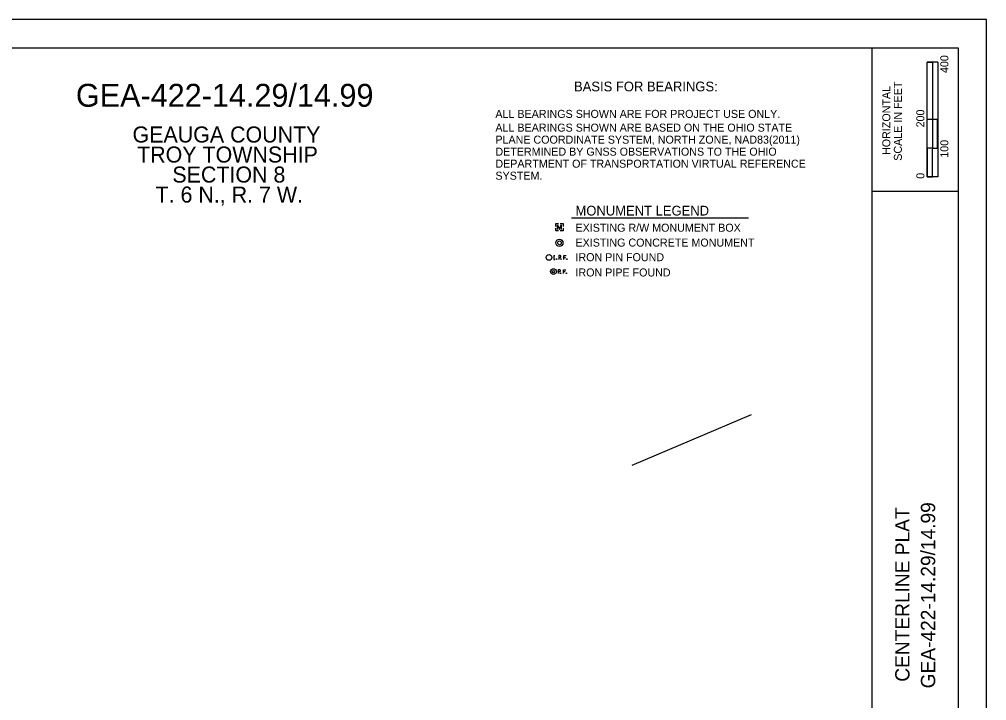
# Model space of a CAD drawing. Extents: x -4.4 to 34, y -1.2 to 22.
# Drawn here: x 17.08 to 34, y 10.09 to 22 of the extents above; entities that cross this region are included whole.
import ezdxf

# ---------------------------------------------------------------- set-up
doc = ezdxf.new("R2010")
doc.units = 0
for name, color, linetype in [('DV_X_Section_VMS_Line', 7, 'Continuous'), ('SH_Border', 7, 'Continuous'), ('SH_Cut_Line', 7, 'Continuous'), ('SH_Named_Boundary', 7, 'Continuous'), ('SH_Text', 7, 'Continuous')]:
    doc.layers.add(name, color=color, linetype=linetype)

msp = doc.modelspace()

# ---------------------------------------------------------------- linework, layer by layer
at = {"layer": 'DV_X_Section_VMS_Line'}
msp.add_line((27.797, 14.21), (29.889, 15.092), dxfattribs=at)
at = {"layer": 'SH_Border'}
for p, q in [((32, 0.5), (32, 21.5)), ((32, 19), (33.5, 19))]:
    msp.add_line(p, q, dxfattribs=at)
msp.add_lwpolyline([(1.5, 21.5), (33.5, 21.5), (33.5, 0.5), (1.5, 0.5)], close=True, dxfattribs=at)
at = {"layer": 'SH_Cut_Line'}
for p, q in [((32.957, 19.25), (32.957, 21.25)), ((33.144, 21.25), (32.957, 21.25)), ((32.957, 20.25), (32.957, 21.25)), ((32.957, 21.25), (33.05, 21.25)), ((33.05, 21.25), (33.051, 21.25)), ((33.051, 21.25), (33.051, 20.25)), ((33.144, 21.25), (33.144, 19.25)), ((33.051, 20.25), (32.957, 20.25)), ((33.143, 20.25), (33.05, 20.25)), ((33.05, 20.25), (33.05, 19.75)), ((33.143, 19.75), (33.143, 20.25)), ((33.05, 19.75), (32.957, 19.75)), ((32.957, 19.75), (32.957, 19.25)), ((33.05, 19.25), (33.05, 19.75)), ((33.05, 19.75), (33.143, 19.75)), ((33.144, 19.25), (32.957, 19.25)), ((32.957, 19.25), (33.05, 19.25))]:
    msp.add_line(p, q, dxfattribs=at)
at = {"layer": 'SH_Named_Boundary'}
msp.add_lwpolyline([(0, 0), (34, 0), (34, 22), (0, 22)], close=True, dxfattribs=at)
at = {"layer": 'SH_Text'}
for p, q in [((26.739, 18.534), (29.832, 18.534)), ((26.527, 18.368), (26.527, 18.368)), ((26.429, 17.873), (26.445, 17.873)), ((26.429, 17.873), (26.445, 17.873)), ((26.429, 17.806), (26.445, 17.806)), ((26.437, 17.806), (26.437, 17.873)), ((26.514, 17.841), (26.54, 17.841)), ((26.607, 17.806), (26.607, 17.873)), ((26.607, 17.873), (26.646, 17.873)), ((26.607, 17.841), (26.635, 17.841)), ((26.6, 17.559), (26.6, 17.625)), ((26.6, 17.625), (26.638, 17.625)), ((26.506, 17.593), (26.533, 17.593)), ((26.6, 17.593), (26.627, 17.593))]:
    msp.add_line(p, q, dxfattribs=at)
for points in [[(26.465, 18.383), (26.465, 18.43), (26.512, 18.43)], [(26.512, 18.305), (26.465, 18.305), (26.465, 18.352)], [(26.496, 18.326), (26.496, 18.409), (26.527, 18.326), (26.558, 18.409), (26.558, 18.326)], [(26.542, 18.43), (26.59, 18.43), (26.59, 18.383)], [(26.59, 18.352), (26.59, 18.305), (26.542, 18.305)], [(26.54, 17.873), (26.514, 17.873), (26.514, 17.806)], [(26.533, 17.625), (26.506, 17.625), (26.506, 17.559)]]:
    msp.add_lwpolyline(points, dxfattribs=at)
for centre, radius in [((26.527, 18.095), 0.0625), ((26.527, 18.095), 0.0333), ((26.345, 17.84), 0.05), ((26.477, 17.811), 0.00583), ((26.554, 17.811), 0.00583), ((26.656, 17.811), 0.00583), ((26.423, 17.592), 0.05), ((26.423, 17.592), 0.0206), ((26.547, 17.563), 0.00583), ((26.648, 17.563), 0.00583)]:
    msp.add_circle(centre, radius, dxfattribs=at)
for centre in [(26.538, 17.857), (26.531, 17.609)]:
    msp.add_arc(centre, 0.0162, 278.8803, 81.1197, dxfattribs=at)

# ---------------------------------------------------------------- texts
at = {"layer": 'SH_Cut_Line'}
for s, height, p in [('400', 0.14, (33.33, 21.062)), ('HORIZONTAL', 0.14, (32.315, 19.63)), ('SCALE IN FEET', 0.14, (32.517, 19.529)), ('200', 0.14, (32.91, 20.112)), ('100', 0.14, (33.33, 19.582)), ('0', 0.14, (32.91, 19.214)), ('GEA-422-14.29/14.99', 0.25, (33.1, 10.309)), ('CENTERLINE PLAT', 0.25, (32.65, 10.425))]:
    msp.add_text(s, height=height, rotation=90, dxfattribs=at).set_placement(p)
at = {"layer": 'SH_Text'}
for s, height, p in [('GEA-422-14.29/14.99', 0.4, (18.07, 20.473)), ('BASIS FOR BEARINGS:', 0.17, (26.782, 20.742)), ('ALL BEARINGS SHOWN ARE FOR PROJECT USE ONLY.', 0.14, (25.407, 20.278)), ('ALL BEARINGS SHOWN ARE BASED ON THE OHIO STATE', 0.14, (25.407, 20.038)), ('GEAUGA COUNTY', 0.28, (19.06, 19.848)), ('PLANE COORDINATE SYSTEM, NORTH ZONE, NAD83(2011)', 0.14, (25.407, 19.828)), ('TROY TOWNSHIP', 0.28, (19.14, 19.498)), ('DETERMINED BY GNSS OBSERVATIONS TO THE OHIO', 0.14, (25.407, 19.618)), ('DEPARTMENT OF TRANSPORTATION VIRTUAL REFERENCE', 0.14, (25.407, 19.408)), ('SECTION 8', 0.28, (19.757, 19.148)), ('SYSTEM.', 0.14, (25.407, 19.198)), ('T. 6 N., R. 7 W.', 0.28, (19.463, 18.798)), ('MONUMENT LEGEND', 0.17, (26.808, 18.572)), ('EXISTING R/W MONUMENT BOX', 0.14, (26.808, 18.289)), ('EXISTING CONCRETE MONUMENT', 0.14, (26.808, 18.029)), ('IRON PIN FOUND', 0.14, (26.808, 17.774)), ('IRON PIPE FOUND', 0.14, (26.808, 17.507))]:
    msp.add_text(s, height=height, dxfattribs=at).set_placement(p)

doc.saveas('drawing.dxf')
